(* Logix 5000 project; controller NXFE2_EDS_AOI_sample_RSLogix_V31 vendor 1 type 14 code 92 rev 31.11; software revision 31.00 *)

TASK MainTask (continuous, watchdog 500 ms) : MainProgram

MODULES
   Local : vendor 1 type 14 code 92 (ICP 0, rev 31.11)
      EN2TR : vendor 1 type 12 code 200 (ICP 2, Ethernet 192.168.0.5, rev 10.1)
         AMCI_NXFE2 : vendor 10 type 12 code 49 (Ethernet 192.168.0.50, rev 1.21, StandardDataDriven RPI 8 ms)
END_MODULES

TYPE ANG1_Driver_Command :
STRUCT
   Absolute_move : BOOL;
   Relative_move : BOOL;
   Hold_move : BOOL;
   Resume_move : BOOL;
   Immediate_stop : BOOL;
   Find_Home_CW : BOOL;
   Find_Home_CCW : BOOL;
   CW_Manual_Move : BOOL;
   CCW_Manual_Move : BOOL;
   Preset_Motor_Position : BOOL;
   Reset_Errors : BOOL;
   Program_Assembled_Move : BOOL;
   Program_Assembled_Move_segments : BOOL;
   Run_Assembled_Move : BOOL;
   Preset_Encoder : BOOL;
   Mode_bit : BOOL;   // "0"=command mode, "1" = configuraiton mode
   Motor_Current_Key0 : BOOL;
   Motor_Current_Key1 : BOOL;
   Encoder_move : BOOL;
   Reserved_bit_3 : BOOL;
   Blend_Move_Direction : BOOL;
   Reserved_bit_5 : BOOL;
   Enable_Electronic_Gearing : BOOL;
   Reserved_bit_7 : BOOL;
   Reserved_bit_8 : BOOL;
   Reserved_bit_9 : BOOL;
   Reserved_bit_10 : BOOL;
   Home_Proximity_Bit : BOOL;
   Reserved_bit_12 : BOOL;
   General_Purpose_output : BOOL;
   Reserved_bit_14 : BOOL;
   Drive_Enable : BOOL;   // "0" to disable motor current, "1" to enable motor current
   upper_target_position : INT;
   lower_target_position : INT;
   upper_programmed_speed : INT;
   lower_programmed_speed : INT;
   Acceleration : INT;   // 1 to 5000 steps/ms/sec
   Decleration : INT;   // 1 to 5000 steps/ms/sec
   Motor_Current : INT;   // 10 to 40, represents 1.0 to 4.0 amps rms
   acceleration_jerk : INT;   // 0 to 5000
END_STRUCT
END_TYPE

TYPE ANG1_Driver_Configuration :
STRUCT
   Input_1_bit_0 : BOOL;
   Input_1_bit_1 : BOOL;
   Input_1_bit_2 : BOOL;
   Input_2_bit_3 : BOOL;
   Input_2_bit_4 : BOOL;
   Input_2_bit_5 : BOOL;
   Input_3_bit_6 : BOOL;
   Input_3_bit_7 : BOOL;
   Input_3_bit_8 : BOOL;
   Reserved_bit_9 : BOOL;
   Quad_encoder_enable : BOOL;   // "0" when Quadrature Encoder is not used, "1" when Quadrature is used
   Home_Proximity_enable : BOOL;   // "0" when the Home Proximity bit is not used, "1" when the Home Proximity will be used
   Reserved_bit_12 : BOOL;
   Stall_detection_enable : BOOL;   // "0' disables Stall Detection, "1" enables Stall Detection
   Anti_resonance_enable : BOOL;   // "0" Enables Antiresonance, "1" Disables Antiresonance
   Mode_bit : BOOL;   // "1"=configuration mode, "0" = command mode
   Input_1_Active_state : BOOL;   // "0" = normally closed, "1" = normally open
   Input_2_Active_state : BOOL;   // "0" = normally closed, "1" = normally open
   Input_3_Active_state : BOOL;   // "0" = normally closed, "1" = normally open
   Reserved_bit_3 : BOOL;
   Reserved_bit_4 : BOOL;
   Reserved_bit_5 : BOOL;
   Reserved_bit_6 : BOOL;
   Reserved_bit_7 : BOOL;
   Reserved_bit_8 : BOOL;
   _Reserved_bit_9 : BOOL;
   Reserved_bit_10 : BOOL;
   Reserved_bit_11 : BOOL;
   Output_state_when_network_lost : BOOL;
   Program_output_state_when_network_lost : BOOL;
   Output_Functionality : BOOL;   // "0"=Fault Output, "1" = General Purpose Output
   Drive_Enable : BOOL;   // "0"=Disabled, "1"=Enabled
   Upper_Starting_Speed : INT;   // 0 to 999
   Lower_Starting_Speed : INT;   // 0 to 999
   Motor_Steps_Turn : INT;   // 200 to 32767
   Reserved_word_5 : INT;
   Encoder_pulses_turn : INT;   // 0 to 32,768
   Idle_current_percentage : INT;   // 0 to 100%
   Motor_Current_X10 : INT;   // 10 to 40, represents 1.0 to 4.0 amps rms
   Current_loop_gain : INT;   // 1 to 40
END_STRUCT
END_TYPE

ADD_ON_INSTRUCTION AMCI_NXFE2_Absolute_Move   (* revision 1.0, vendor AMCI, ExecuteEnableInFalse *)
VAR_INPUT
   Axis_Status_Bits : INT; {required}
   _0_normal_1_S_curve_acceleration : BOOL;
   _0_triangular_1_trapezoidal_S_curve : BOOL;
   Target_Position : DINT; {required}
   Programmed_Speed : DINT; {required}
   Acceleration : INT; {required}
   Deceleration : INT; {required}
END_VAR
VAR_IN_OUT
   NXFE2_output_data : _000A:NXFE2_0986AEB4:O:0; {required}
END_VAR
VAR_OUTPUT
   EN : BOOL; {access Read Only, visible}
   ER : BOOL; {access Read Only, visible}
END_VAR
VAR
   command_data_block : INT[10];
        [0]   // Command Bits MSW
        [3]   // Lower Target Position
        [1]   // Command Bits LSW
        [5]   // Lower Programmed Speed
        [2]   // Upper Target Position
        [4]   // Upper Programmed Speed
END_VAR

ROUTINE EnableInFalse   (* ladder *)
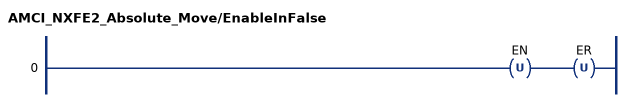
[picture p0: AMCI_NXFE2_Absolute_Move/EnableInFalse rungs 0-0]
   0: OTU(EN)OTU(ER);
END_ROUTINE

ROUTINE Logic   (* ladder *)
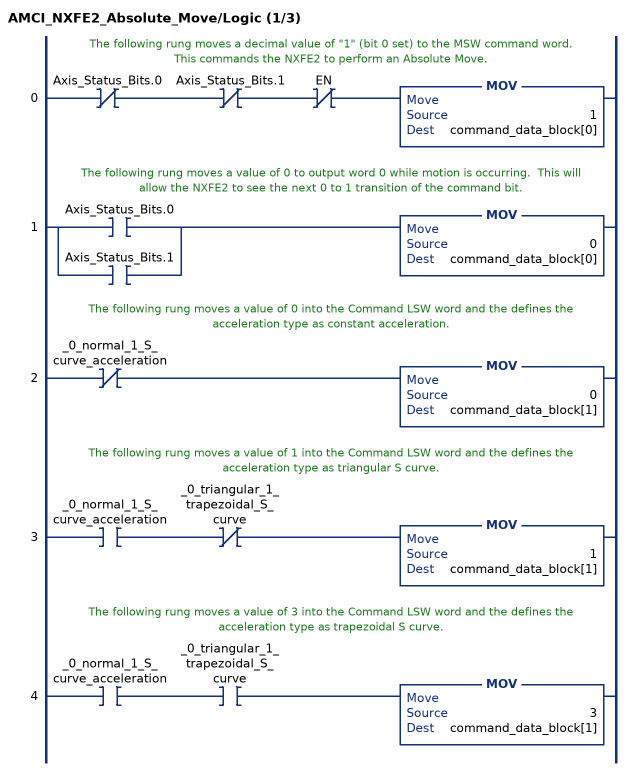
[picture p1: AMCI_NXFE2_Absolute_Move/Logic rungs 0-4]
   // The following rung moves a decimal value of "1" (bit 0 set) to the MSW command word.  This commands the NXFE2 to perform an Absolute Move.
   0: XIO(Axis_Status_Bits.0)XIO(Axis_Status_Bits.1)XIO(EN)MOV(1,command_data_block[0]);
   // The following rung moves a value of 0 to output word 0 while motion is occurring.  This will allow the NXFE2 to see the next 0 to 1 transition of the command bit.
   1: [XIC(Axis_Status_Bits.0) ,XIC(Axis_Status_Bits.1) ]MOV(0,command_data_block[0]);
   // The following rung moves a value of 0 into the Command LSW word and the defines the acceleration type as constant acceleration.
   2: XIO(_0_normal_1_S_curve_acceleration)MOV(0,command_data_block[1]);
   // The following rung moves a value of 1 into the Command LSW word and the defines the acceleration type as triangular S curve.
   3: XIC(_0_normal_1_S_curve_acceleration)XIO(_0_triangular_1_trapezoidal_S_curve)MOV(1,command_data_block[1]);
   // The following rung moves a value of 3 into the Command LSW word and the defines the acceleration type as trapezoidal S curve.
   4: XIC(_0_normal_1_S_curve_acceleration)XIC(_0_triangular_1_trapezoidal_S_curve)MOV(3,command_data_block[1]);
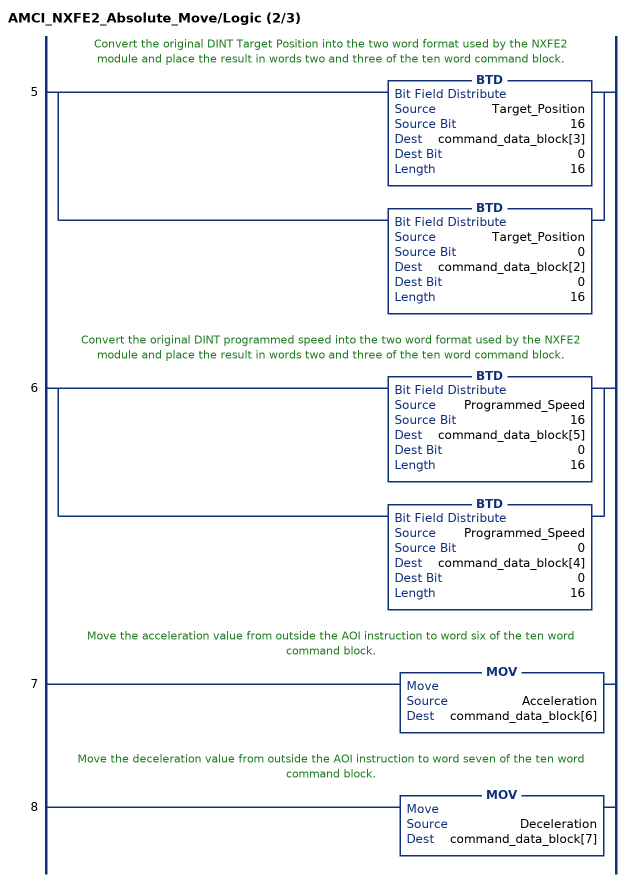
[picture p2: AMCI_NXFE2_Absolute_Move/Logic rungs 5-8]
   // Convert the original DINT Target Position into the two word format used by the NXFE2 module and place the result in words two and three of the ten word command block.
   5: [BTD(Target_Position,16,command_data_block[3],0,16) ,BTD(Target_Position,0,command_data_block[2],0,16) ];
   // Convert the original DINT programmed speed into the two word format used by the NXFE2 module and place the result in words two and three of the ten word command block.
   6: [BTD(Programmed_Speed,16,command_data_block[5],0,16) ,BTD(Programmed_Speed,0,command_data_block[4],0,16) ];
   // Move the acceleration value from outside the AOI instruction to word six of the ten word command block.
   7: MOV(Acceleration,command_data_block[6]);
   // Move the deceleration value from outside the AOI instruction to word seven of the ten word command block.
   8: MOV(Deceleration,command_data_block[7]);
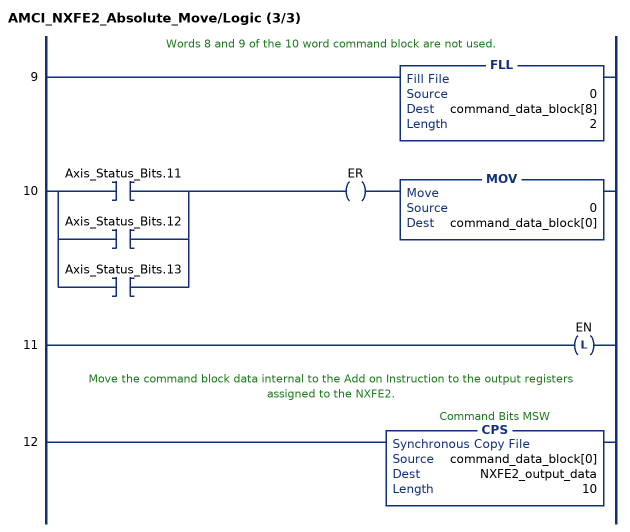
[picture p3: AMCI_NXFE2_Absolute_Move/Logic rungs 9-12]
   // Words 8 and 9 of the 10 word command block are not used.
   9: FLL(0,command_data_block[8],2);
   10: [XIC(Axis_Status_Bits.11) ,XIC(Axis_Status_Bits.12) ,XIC(Axis_Status_Bits.13) ]OTE(ER)MOV(0,command_data_block[0]);
   11: OTL(EN);
   // Move the command block data internal to the Add on Instruction to the output registers assigned to the NXFE2.
   12: CPS(command_data_block[0],NXFE2_output_data,10);
END_ROUTINE
END_ADD_ON_INSTRUCTION

ADD_ON_INSTRUCTION AMCI_NXFE2_Configure   (* revision 1.0 *)
VAR_INPUT
   capture_input : BOOL; {required}
   capture_input_active_state : BOOL; {required}
   external_input : BOOL; {required}
   external_input_active_state : BOOL; {required}
   home_input : BOOL; {required}
   home_input_active_state : BOOL; {required}
   _1_CW_limit_2_estop : INT; {required}
   CW_estop_actitve_state : BOOL; {required}
   _1_CCW_limit_2_estop : INT; {required}
   CCW_estop_active_state : BOOL; {required}
   Backplane_Home_Proximity_Enable : BOOL;
   Quadrature_Encoder_Enable : BOOL; {required}
   diagnostic_feedback_enable : BOOL;
   _0_CW_CCW_1_step_direction : BOOL; {required}
   _0_Limit_Switch_1_Marker_Pulse_home : BOOL;
   swap_32_bit_word_order : BOOL;
   disable_channel : BOOL;
   Starting_Speed : DINT; {required}
   homing_timeout : INT; {required}
END_VAR
VAR_IN_OUT
   NXFE2_output_data : _000A:NXFE2_0986AEB4:O:0; {required}
END_VAR
VAR
   command_data_block : INT[10];
        [0].15   // Mode Bit 1=Configuraiton Mode 0=Command Mode
END_VAR

ROUTINE Logic   (* ladder *)
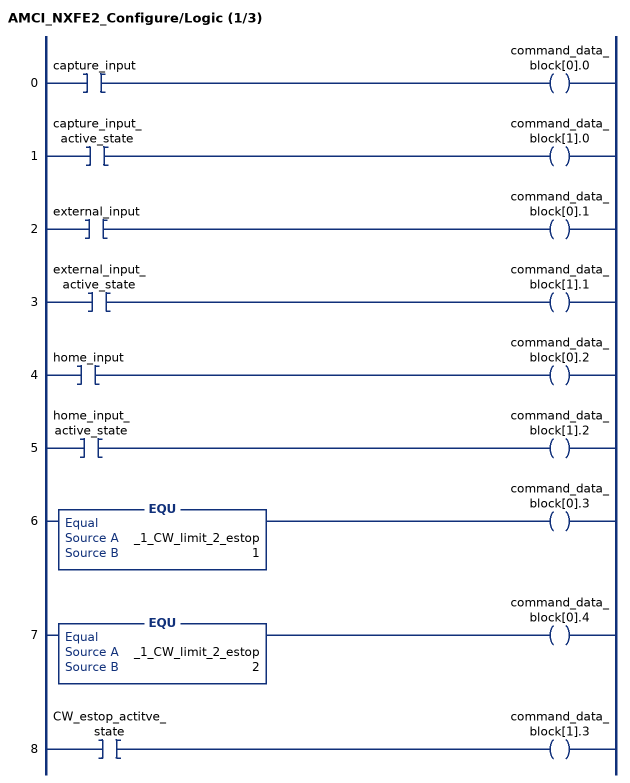
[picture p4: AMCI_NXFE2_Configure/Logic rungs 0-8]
   0: XIC(capture_input)OTE(command_data_block[0].0);
   1: XIC(capture_input_active_state)OTE(command_data_block[1].0);
   2: XIC(external_input)OTE(command_data_block[0].1);
   3: XIC(external_input_active_state)OTE(command_data_block[1].1);
   4: XIC(home_input)OTE(command_data_block[0].2);
   5: XIC(home_input_active_state)OTE(command_data_block[1].2);
   6: EQU(_1_CW_limit_2_estop,1)OTE(command_data_block[0].3);
   7: EQU(_1_CW_limit_2_estop,2)OTE(command_data_block[0].4);
   8: XIC(CW_estop_actitve_state)OTE(command_data_block[1].3);
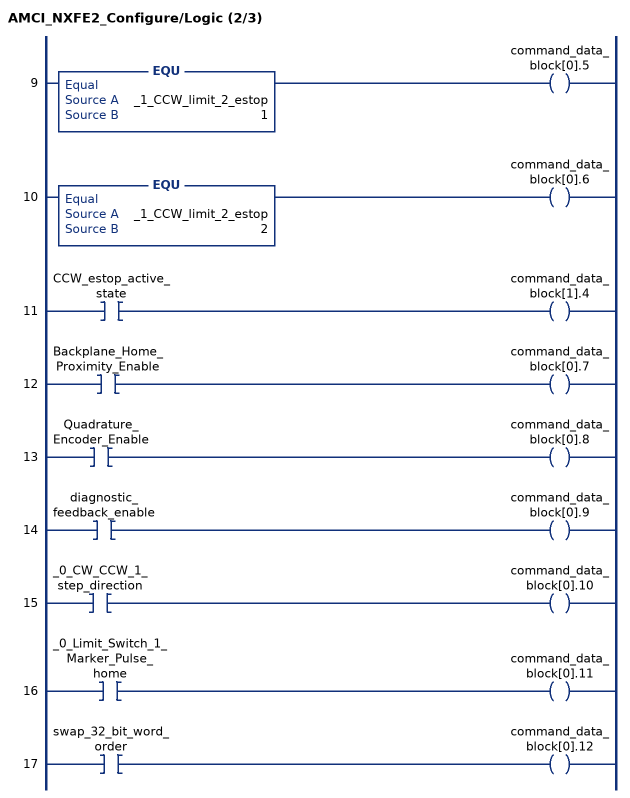
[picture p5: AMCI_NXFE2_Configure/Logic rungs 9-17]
   9: EQU(_1_CCW_limit_2_estop,1)OTE(command_data_block[0].5);
   10: EQU(_1_CCW_limit_2_estop,2)OTE(command_data_block[0].6);
   11: XIC(CCW_estop_active_state)OTE(command_data_block[1].4);
   12: XIC(Backplane_Home_Proximity_Enable)OTE(command_data_block[0].7);
   13: XIC(Quadrature_Encoder_Enable)OTE(command_data_block[0].8);
   14: XIC(diagnostic_feedback_enable)OTE(command_data_block[0].9);
   15: XIC(_0_CW_CCW_1_step_direction)OTE(command_data_block[0].10);
   16: XIC(_0_Limit_Switch_1_Marker_Pulse_home)OTE(command_data_block[0].11);
   17: XIC(swap_32_bit_word_order)OTE(command_data_block[0].12);
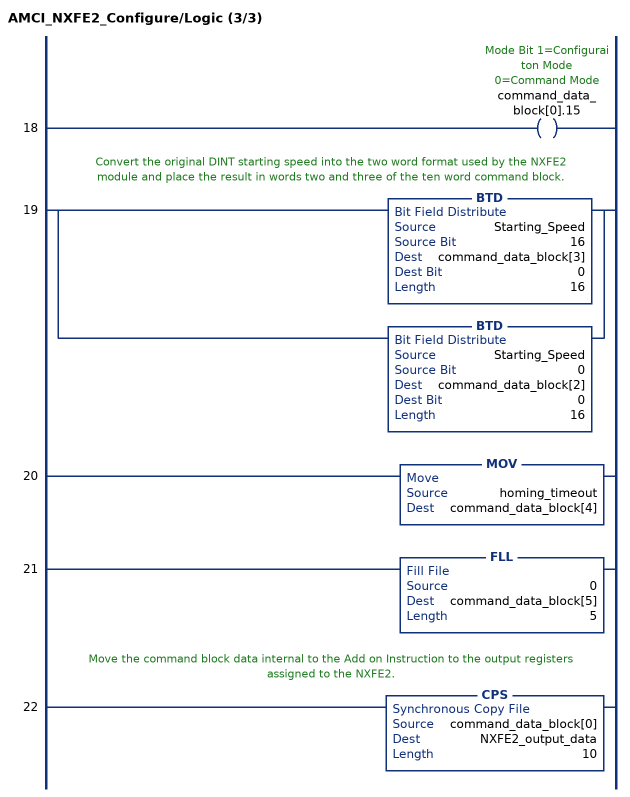
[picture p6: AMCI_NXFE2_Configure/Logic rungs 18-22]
   18: OTE(command_data_block[0].15);
   // Convert the original DINT starting speed into the two word format used by the NXFE2 module and place the result in words two and three of the ten word command block.
   19: [BTD(Starting_Speed,16,command_data_block[3],0,16) ,BTD(Starting_Speed,0,command_data_block[2],0,16) ];
   20: MOV(homing_timeout,command_data_block[4]);
   21: FLL(0,command_data_block[5],5);
   // Move the command block data internal to the Add on Instruction to the output registers assigned to the NXFE2.
   22: CPS(command_data_block[0],NXFE2_output_data,10);
END_ROUTINE
END_ADD_ON_INSTRUCTION

ADD_ON_INSTRUCTION AMCI_NXFE2_Encoder_Follower_CCW   (* revision 1.0, vendor AMCI, ExecuteEnableInFalse *)
VAR_INPUT
   Axis_Status_Bits : INT; {required}
   _0_normal_1_S_curve_acceleration : BOOL;
   _0_Triangular_1_Trapezoidal_S_Curve : BOOL;
   Encoder_Count_Multiplier : INT; {required}
   Encoder_count_Divisor : INT; {required}
   Acceleration : INT; {required}
   Deceleration : INT; {required}
END_VAR
VAR_IN_OUT
   NXFE2_output_data : _000A:NXFE2_0986AEB4:O:0; {required}
END_VAR
VAR_OUTPUT
   EN : BOOL; {access Read Only, visible}
   Encoder_Follower_Occurring : BOOL; {access Read Only, visible}
   ER : BOOL; {access Read Only, visible}
END_VAR
VAR
   command_data_block : INT[10];
        [1]   // Command Bits LSW
        [0]   // Command Bits MSW
        [5]   // Lower Programmed Speed
        [4]   // Upper Programmed Speed
END_VAR

ROUTINE EnableInFalse   (* ladder *)
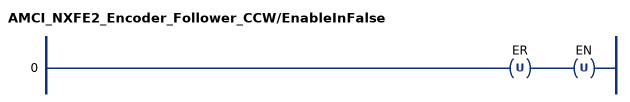
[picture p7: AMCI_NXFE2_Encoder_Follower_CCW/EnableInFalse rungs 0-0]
   0: OTU(ER)OTU(EN);
END_ROUTINE

ROUTINE Logic   (* ladder *)
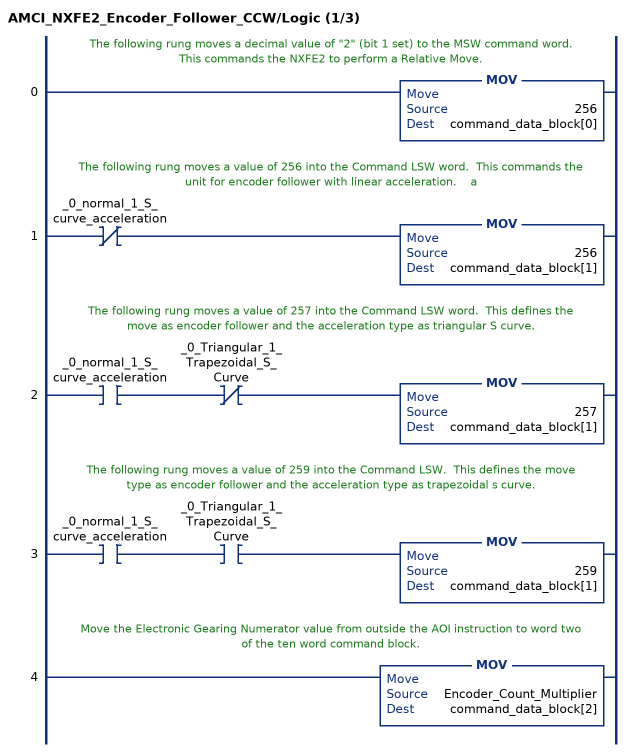
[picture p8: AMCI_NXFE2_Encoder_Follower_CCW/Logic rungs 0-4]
   // The following rung moves a decimal value of "2" (bit 1 set) to the MSW command word.  This commands the NXFE2 to perform a Relative Move.
   0: MOV(256,command_data_block[0]);
   // The following rung moves a value of 256 into the Command LSW word.  This commands the unit for encoder follower with linear acceleration.    a
   1: XIO(_0_normal_1_S_curve_acceleration)MOV(256,command_data_block[1]);
   // The following rung moves a value of 257 into the Command LSW word.  This defines the move as encoder follower and the acceleration type as triangular S curve.
   2: XIC(_0_normal_1_S_curve_acceleration)XIO(_0_Triangular_1_Trapezoidal_S_Curve)MOV(257,command_data_block[1]);
   // The following rung moves a value of 259 into the Command LSW.  This defines the move type as encoder follower and the acceleration type as trapezoidal s curve.
   3: XIC(_0_normal_1_S_curve_acceleration)XIC(_0_Triangular_1_Trapezoidal_S_Curve)MOV(259,command_data_block[1]);
   // Move the Electronic Gearing Numerator value from outside the AOI instruction to word two of the ten word command block.
   4: MOV(Encoder_Count_Multiplier,command_data_block[2]);
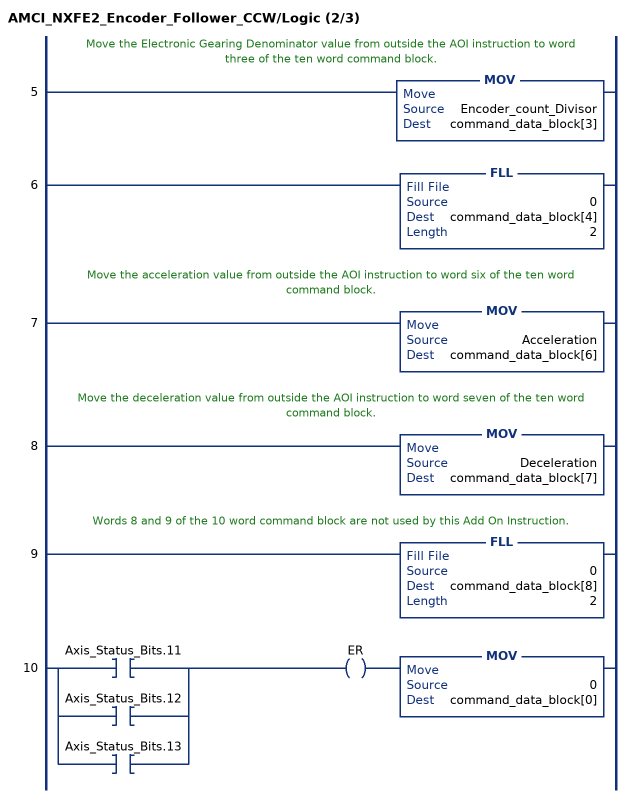
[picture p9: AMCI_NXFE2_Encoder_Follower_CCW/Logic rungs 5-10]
   // Move the Electronic Gearing Denominator value from outside the AOI instruction to word three of the ten word command block.
   5: MOV(Encoder_count_Divisor,command_data_block[3]);
   6: FLL(0,command_data_block[4],2);
   // Move the acceleration value from outside the AOI instruction to word six of the ten word command block.
   7: MOV(Acceleration,command_data_block[6]);
   // Move the deceleration value from outside the AOI instruction to word seven of the ten word command block.
   8: MOV(Deceleration,command_data_block[7]);
   // Words 8 and 9 of the 10 word command block are not used by this Add On Instruction.
   9: FLL(0,command_data_block[8],2);
   10: [XIC(Axis_Status_Bits.11) ,XIC(Axis_Status_Bits.12) ,XIC(Axis_Status_Bits.13) ]OTE(ER)MOV(0,command_data_block[0]);
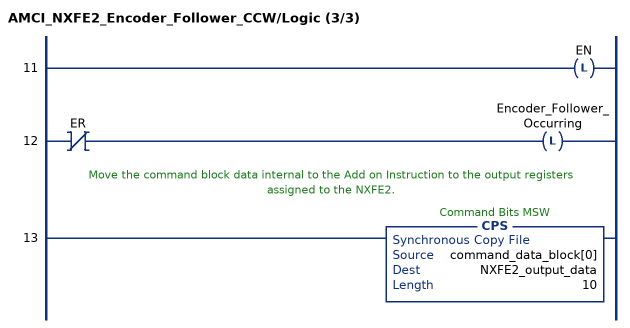
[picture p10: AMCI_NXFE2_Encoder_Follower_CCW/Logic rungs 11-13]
   11: OTL(EN);
   12: XIO(ER)OTL(Encoder_Follower_Occurring);
   // Move the command block data internal to the Add on Instruction to the output registers assigned to the NXFE2.
   13: CPS(command_data_block[0],NXFE2_output_data,10);
END_ROUTINE
END_ADD_ON_INSTRUCTION

ADD_ON_INSTRUCTION AMCI_NXFE2_Encoder_Follower_CW   (* revision 1.0, vendor AMCI, ExecuteEnableInFalse *)
VAR_INPUT
   Axis_Status_Bits : INT; {required}
   _0_normal_1_S_curve_acceleration : BOOL;
   _0_Triangular_1_Trapezoidal_S_Curve : BOOL;
   Encoder_Count_Multiplier : INT; {required}
   Encoder_count_Divisor : INT; {required}
   Acceleration : INT; {required}
   Deceleration : INT; {required}
END_VAR
VAR_IN_OUT
   NXFE2_output_data : _000A:NXFE2_0986AEB4:O:0; {required}
END_VAR
VAR_OUTPUT
   EN : BOOL; {access Read Only, visible}
   Encoder_Follower_Occurring : BOOL; {access Read Only, visible}
   ER : BOOL; {access Read Only, visible}
END_VAR
VAR
   command_data_block : INT[10];
        [5]   // Lower Programmed Speed
        [4]   // Upper Programmed Speed
        [1]   // Command Bits LSW
        [0]   // Command Bits MSW
END_VAR

ROUTINE EnableInFalse   (* ladder *)
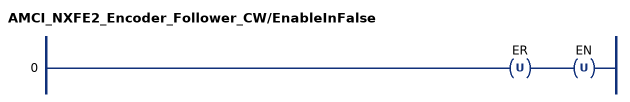
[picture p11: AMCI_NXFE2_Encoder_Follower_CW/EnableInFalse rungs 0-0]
   0: OTU(ER)OTU(EN);
END_ROUTINE

ROUTINE Logic   (* ladder *)
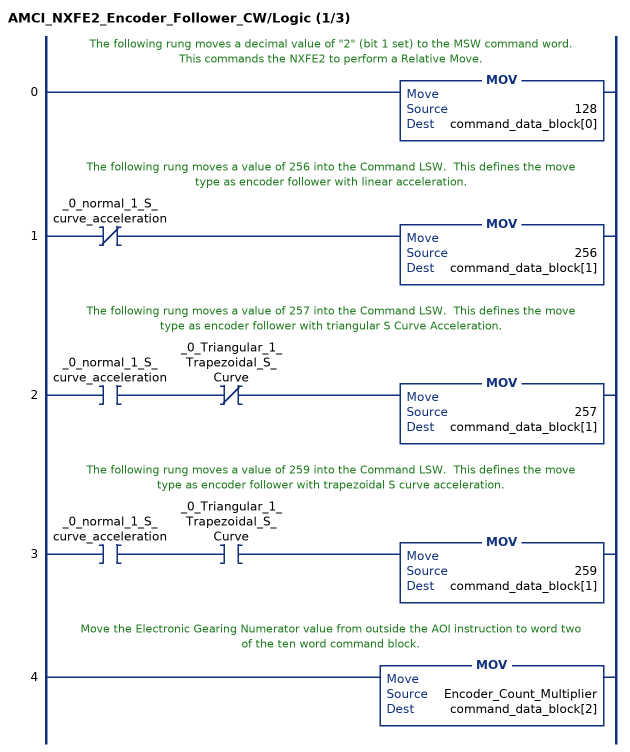
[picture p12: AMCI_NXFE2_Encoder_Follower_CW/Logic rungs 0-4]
   // The following rung moves a decimal value of "2" (bit 1 set) to the MSW command word.  This commands the NXFE2 to perform a Relative Move.
   0: MOV(128,command_data_block[0]);
   // The following rung moves a value of 256 into the Command LSW.  This defines the move type as encoder follower with linear acceleration.
   1: XIO(_0_normal_1_S_curve_acceleration)MOV(256,command_data_block[1]);
   // The following rung moves a value of 257 into the Command LSW.  This defines the move type as encoder follower with triangular S Curve Acceleration.
   2: XIC(_0_normal_1_S_curve_acceleration)XIO(_0_Triangular_1_Trapezoidal_S_Curve)MOV(257,command_data_block[1]);
   // The following rung moves a value of 259 into the Command LSW.  This defines the move type as encoder follower with trapezoidal S curve acceleration.
   3: XIC(_0_normal_1_S_curve_acceleration)XIC(_0_Triangular_1_Trapezoidal_S_Curve)MOV(259,command_data_block[1]);
   // Move the Electronic Gearing Numerator value from outside the AOI instruction to word two of the ten word command block.
   4: MOV(Encoder_Count_Multiplier,command_data_block[2]);
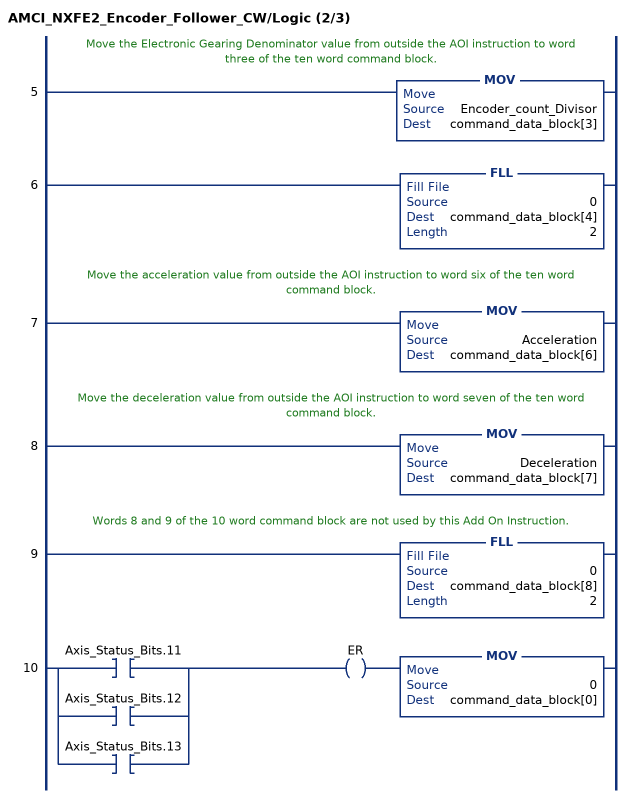
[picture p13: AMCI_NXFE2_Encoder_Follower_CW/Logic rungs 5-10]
   // Move the Electronic Gearing Denominator value from outside the AOI instruction to word three of the ten word command block.
   5: MOV(Encoder_count_Divisor,command_data_block[3]);
   6: FLL(0,command_data_block[4],2);
   // Move the acceleration value from outside the AOI instruction to word six of the ten word command block.
   7: MOV(Acceleration,command_data_block[6]);
   // Move the deceleration value from outside the AOI instruction to word seven of the ten word command block.
   8: MOV(Deceleration,command_data_block[7]);
   // Words 8 and 9 of the 10 word command block are not used by this Add On Instruction.
   9: FLL(0,command_data_block[8],2);
   10: [XIC(Axis_Status_Bits.11) ,XIC(Axis_Status_Bits.12) ,XIC(Axis_Status_Bits.13) ]OTE(ER)MOV(0,command_data_block[0]);
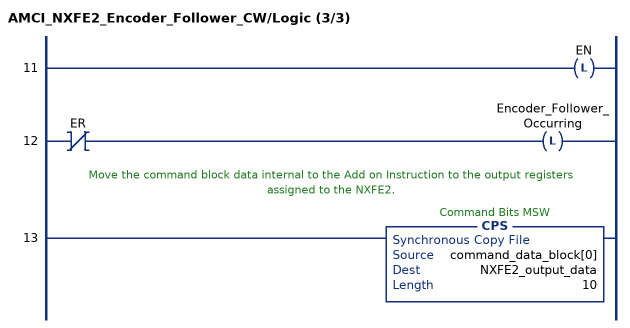
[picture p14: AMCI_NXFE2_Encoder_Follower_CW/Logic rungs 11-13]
   11: OTL(EN);
   12: XIO(ER)OTL(Encoder_Follower_Occurring);
   // Move the command block data internal to the Add on Instruction to the output registers assigned to the NXFE2.
   13: CPS(command_data_block[0],NXFE2_output_data,10);
END_ROUTINE
END_ADD_ON_INSTRUCTION

ADD_ON_INSTRUCTION AMCI_NXFE2_Hold   (* revision 1.0, vendor AMCI *)
VAR_IN_OUT
   NXFE2_output_data : _000A:NXFE2_0986AEB4:O:0; {required}
END_VAR
VAR
   command_data_block : INT[10];
        [5]   // Lower Programmed Speed
        [0]   // Command Bits MSW
        [1]   // Command Bits LSW
        [3]   // Lower Target Position
        [2]   // Upper Target Position
        [4]   // Upper Programmed Speed
END_VAR

ROUTINE Logic   (* ladder *)
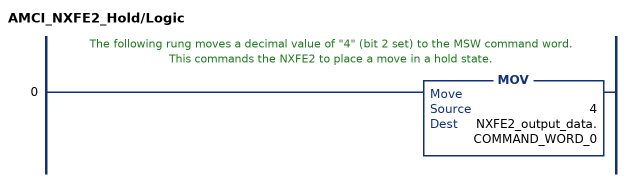
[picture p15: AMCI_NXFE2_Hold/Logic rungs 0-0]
   // The following rung moves a decimal value of "4" (bit 2 set) to the MSW command word.  This commands the NXFE2 to place a move in a hold state.
   0: MOV(4,NXFE2_output_data.COMMAND_WORD_0);
END_ROUTINE
END_ADD_ON_INSTRUCTION

ADD_ON_INSTRUCTION AMCI_NXFE2_Home_CCW   (* revision 1.0, vendor AMCI, ExecuteEnableInFalse *)
VAR_INPUT
   Axis_Status_Bits : INT; {required}
   Programmed_Speed : DINT; {required}
   Acceleration : INT; {required}
   Deceleration : INT; {required}
END_VAR
VAR_IN_OUT
   NXFE2_output_data : _000A:NXFE2_0986AEB4:O:0; {required}
END_VAR
VAR_OUTPUT
   EN : BOOL; {access Read Only, visible}
   ER : BOOL; {access Read Only, visible}
END_VAR
VAR
   Upper_Result_X_1000 : DINT;
   command_data_block : INT[10];
        [1]   // Command Bits LSW
        [5]   // Lower Programmed Speed
        [0]   // Command Bits MSW
        [3]   // Lower Target Position
        [2]   // Upper Target Position
        [4]   // Upper Programmed Speed
   index : INT;
END_VAR

ROUTINE EnableInFalse   (* ladder *)
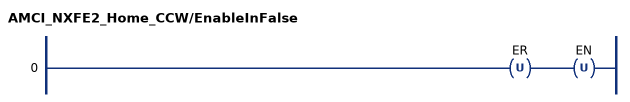
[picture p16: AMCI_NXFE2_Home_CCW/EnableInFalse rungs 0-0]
   0: OTU(ER)OTU(EN);
END_ROUTINE

ROUTINE Logic   (* ladder *)
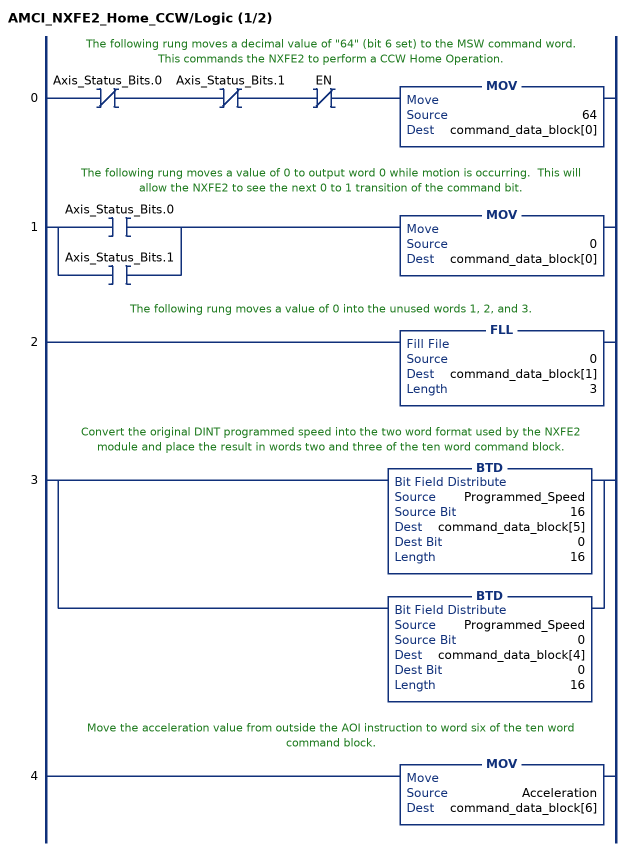
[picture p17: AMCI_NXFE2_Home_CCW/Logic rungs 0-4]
   // The following rung moves a decimal value of "64" (bit 6 set) to the MSW command word.  This commands the NXFE2 to perform a CCW Home Operation.
   0: XIO(Axis_Status_Bits.0)XIO(Axis_Status_Bits.1)XIO(EN)MOV(64,command_data_block[0]);
   // The following rung moves a value of 0 to output word 0 while motion is occurring.  This will allow the NXFE2 to see the next 0 to 1 transition of the command bit.
   1: [XIC(Axis_Status_Bits.0) ,XIC(Axis_Status_Bits.1) ]MOV(0,command_data_block[0]);
   // The following rung moves a value of 0 into the unused words 1, 2, and 3.
   2: FLL(0,command_data_block[1],3);
   // Convert the original DINT programmed speed into the two word format used by the NXFE2 module and place the result in words two and three of the ten word command block.
   3: [BTD(Programmed_Speed,16,command_data_block[5],0,16) ,BTD(Programmed_Speed,0,command_data_block[4],0,16) ];
   // Move the acceleration value from outside the AOI instruction to word six of the ten word command block.
   4: MOV(Acceleration,command_data_block[6]);
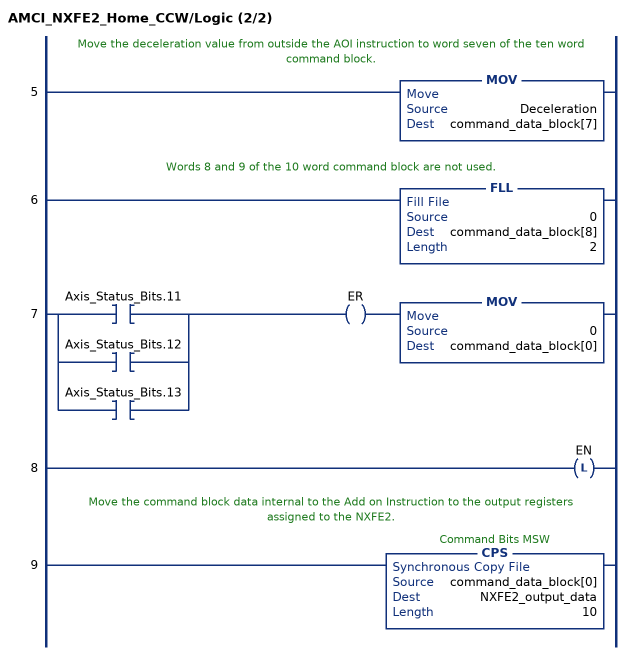
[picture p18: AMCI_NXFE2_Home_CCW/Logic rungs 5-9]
   // Move the deceleration value from outside the AOI instruction to word seven of the ten word command block.
   5: MOV(Deceleration,command_data_block[7]);
   // Words 8 and 9 of the 10 word command block are not used.
   6: FLL(0,command_data_block[8],2);
   7: [XIC(Axis_Status_Bits.11) ,XIC(Axis_Status_Bits.12) ,XIC(Axis_Status_Bits.13) ]OTE(ER)MOV(0,command_data_block[0]);
   8: OTL(EN);
   // Move the command block data internal to the Add on Instruction to the output registers assigned to the NXFE2.
   9: CPS(command_data_block[0],NXFE2_output_data,10);
END_ROUTINE
END_ADD_ON_INSTRUCTION
